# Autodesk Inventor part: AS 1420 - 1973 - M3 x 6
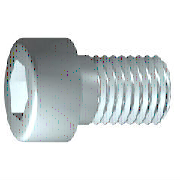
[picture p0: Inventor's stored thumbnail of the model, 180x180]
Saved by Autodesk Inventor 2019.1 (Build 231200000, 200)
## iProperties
Created: 2018-01
Part Number: AS 1420 - 1973 - M3 x 6
Material: Steel, Mild
Description: ISO metric hexagon socket head cap screws
Document SubType Name: Modeling
Standard: AS 1420 - 1973
Designer: drawing
Standards Organization: AS
Language: en-US
Size Designation: M3 x 6
Categories: <MemberInstance><Categories><Category DisplayName="Fasteners" InternalName="e4da775c-781d-43d5-af7c-5136215cf5a6" Mnemonic="FSTN"><Category DisplayName="Bolts"
Density: 7.85 g/cm^3
Appearance: Semi-Polished
IsCustomPart: 0
Author: drawing
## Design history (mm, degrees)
sketch "Sketch1"
  geometry: L1 (-0.867, 0)-(6, 0); L2 (6, 0)-(6, 1.5); L3 (6, 1.5)-(1.25, 1.5); L4 (1.25, 1.5)-(0.943, 1.5); L5 (0.943, 1.5)-(0, 1.5); L6 (0, 1.5)-(0, 2.75); L7 (0, 2.75)-(-3, 2.75); L8 (-3, 2.75)-(-3, 1.443); L9 (-3, 1.443)-(-1.7, 1.443); L10 (-1.7, 1.443)-(-0.867, 0); L11 (-4.8, 0)-(7.8, 0) reference; L12 (0, -0.55)-(0, 3.3) reference; L13 (1.25, 1.5)-(0, 1.5)
  constraints: 22 end point, 6 parallel, 2 collinear, 2 perpendicular, 1 horizontal, 1 point on line
  dimensions: "d1" = 4.75 distance from line of L3.end L2 (= GEL); "d2" = 0.30683 distance of L4.end L3.end (computed from GAL); "d3" = 3 distance between parallel lines of L8 L6 (= KOH); "d4" = 1.3 distance of L8.end L9.end (= INTI); "d5" = 60 deg angle of L10 L1; "d6" = 3 diameter of L3 L1 (= GD); "d7" = 3 diameter of L5 L1 (= BDM); "d8" = 2.88675 diameter of L9 L1 (= 1.1547 x SW); "d9" = 5.5 diameter of L7 L1 (= KOD); "d26" = 6 distance between parallel lines of L12 L2 (= NLG)
revolve "Body" sketch "Sketch1" stored, may be unused: angle "d10" = 90 deg
sketch "Sketch2"
  geometry: L1 (0, -3.85)-(0, 3.85) reference; L2 (-3.85, 0)-(3.85, 0) reference; L3 (1.443, 0)-(0.722, -1.25); L4 (0.722, -1.25)-(-0.722, -1.25); L5 (-0.722, -1.25)-(-1.443, 0); L6 (-1.443, 0)-(-0.722, 1.25); L7 (-0.722, 1.25)-(0.722, 1.25); L8 (0.722, 1.25)-(1.443, 0); 2 further points
  constraints: 12 end point, 1 coincident, 1 horizontal alignment, 1 point on line, 12 other
extrude "Slot" join sketch "Sketch2" stored distance "d11" = 10; taper "d12" = 0 deg
workplane "Work Plane1"
fillet "Fillet2" dims "d30" = 0.1 (= R)
body "Solid1"
fillet "Fillet1" dims "d17" = 0.3 (= RR)
feature "Thread" dims "d13" = 4.75 (= GEL), "d14" = 0
chamfer "Chamfer1" distance "d15" = 0.30673 (= -0.5 x SPD + 0.5 x GD); stored, may be unused: second distance "d16" = 0.30673 (= GUL), angle "d27" = 45 deg
other parameters: "GD" = 3 (= NND) [user parameter; used in 2 equation terms], "NLG" = 6 [user parameter; used in 1 equation term], "GEL" = 4.75 [user parameter; used in 2 equation terms], "KOD" = 5.5 [user parameter; used in 1 equation term], "KOH" = 3 (= NND) [user parameter; used in 1 equation term], "INTI" = 1.3 [user parameter; used in 1 equation term], "GAL" = 0.30673 (= 0.61345 x PTC) [user parameter; used in 1 equation term], "GUL" = 0.30673 (= 0.61345 x PTC) [user parameter; used in 1 equation term], "BDM" = 3 (= NND) [user parameter; used in 1 equation term], "SW" = 2.5 [user parameter; used in 2 equation terms], "RR" = 0.3 (= 0.1 x NND) [user parameter; used in 1 equation term], "SPD" = 2.38655 (= NND - 1.2269 x PTC) [user parameter; used in 1 equation term], "d19" = 0, "d28" = 0, "d29" = 0, "R" = 0.1 [user parameter; used in 1 equation term], "PHH" = 0.13 [user parameter], "GD1" = 2.38655 (= THREADDIA - 1.2269 x PTC) [user parameter], "THREADDIA" = 3 [user parameter; used in 1 equation term], "FAWI" = 45 deg [user parameter], "PTC" = 0.5 [user parameter; used in 5 equation terms], "KOH1" = 2.7 [user parameter], "NND" = 3 [user parameter; used in 5 equation terms], "TOA" = 30 deg [user parameter], "E0" = 2.8875 (= 1.155 x SW) [user parameter]
